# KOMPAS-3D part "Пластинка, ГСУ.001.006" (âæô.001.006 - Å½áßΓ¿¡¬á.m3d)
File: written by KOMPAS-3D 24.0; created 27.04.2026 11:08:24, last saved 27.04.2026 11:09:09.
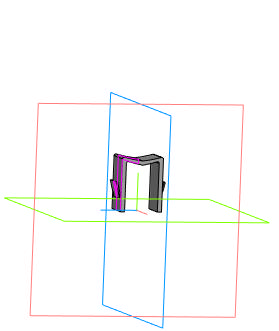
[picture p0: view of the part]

Document properties: Автор: User7; Полное имя файла: C:\Users\User7\Desktop\олимп\ГСУ.001.006 - Пластинка.m3d

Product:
- Part/product: Пластинка  | designation ГСУ.001.006
    Масса: 0.001875

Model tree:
1. Эскиз:1
2. Элемент выдавливания:1
     Расстояние 1 = 7
3. Элемент выдавливания:2
     Расстояние 1 = 5
4. Зеркальный массив:1
5. Экземпляр ( 1 )
6. Экземпляр ( 2 )  (with: Элемент выдавливания:1, Элемент выдавливания:2)
7. Скругление:1  (with: Ребро.Элемент выдавливания:1)  (labels: Ребро.Элемент выдавливания:1.Экземпляр ( 2 ))
     Радиус = 0.4

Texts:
  ГСУ.001.006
